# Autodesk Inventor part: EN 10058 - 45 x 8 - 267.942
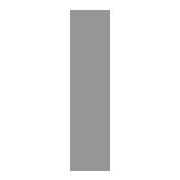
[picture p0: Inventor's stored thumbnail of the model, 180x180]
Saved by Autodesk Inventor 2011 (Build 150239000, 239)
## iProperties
Created: 2010-02
Part Number: EN 10058 - 45 x 8 - 267.942
Material: Steel, Mild
Description: flat steel bar 45*8
Document SubType Name: Modeling
Standard: DIN
Designer: PC
Standard Revision: 2004
Standards Organization: DIN
Language: en-US
Size Designation: 45 x 8
Categories: <MemberInstance><Categories><Category DisplayName="Structural Shapes" InternalName="089c4875-fa83-4c05-b084-43b9cc11f5ed" Mnemonic="GRDR"><CategoryParameter Dis
Stock Number: 45 x 8
Density: 7.86 g/cm^3
IsCustomPart: 1
_CCFamilyMember: 49
_CCFamilyDisplayName: DIN EN 10058 - Hot rolled flat steel bars for general purposes
_FrameMemberDoc: Frame Member File
_Version: 15.0.0
_GetPNFromCC: 1
G_L: 267.942 mm
G_W: 8.000 mm
G_H: 45.000 mm
+CA0FB9A9-289B-43A0-BCB1-81F3ED1C0187+CUTDETAIL1: Cut
Author: PC
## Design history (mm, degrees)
node "Start plane"
node "End plane"
sketch "Sketch"
  geometry: L1 (4, -22.5)-(-4, -22.5); L2 (-4, -22.5)-(-4, 22.5); L3 (-4, 22.5)-(4, 22.5); L4 (4, 22.5)-(4, -22.5); L5 (-6, 0)-(8, 0); L6 (0, -30)-(0, 40); L7 (0, 54)-(0, -44) reference; L8 (-9.2, 0)-(13.2, 0) reference
  constraints: 12 end point, 2 collinear, 2 parallel, 1 horizontal, 1 perpendicular
  dimensions: "d0" = 45 distance between parallel lines of L3 L1 (= G_W); "d1" = 8 distance between parallel lines of L4 L2 (= G_H); "d4" = 4 distance between parallel lines of L6 L4 (= 0.5 x d1); "d5" = 22.5 distance between parallel lines of L5 L3 (= 0.5 x d0)
extrude "Body" new body sketch "Sketch" stored distance "d2" = 267.94229 (= G_L); taper "d3" = 0 deg
node "Driven Length"
  sketch "Sketch3"
    geometry: L1 (0, 0)-(10, 0) reference
    constraints: 2 end point, 1 horizontal
  workplane "Work Plane3"
  sketch "Sketch4"
    geometry: L1 (-2, -167.942)-(12, -167.942) reference; L2 (-2, 100)-(12, 100) reference
    dimensions: "d9" = 267.94229 distance between parallel lines of L1 L2 (derived)
workplane "Work Plane4"
split "Split1"
body "Solid1"
other parameters: "G_W" = 45 [user parameter; used in 1 equation term], "G_H" = 8 [user parameter; used in 1 equation term], "G_L" = 267.94229 (= d9) [user parameter; used in 1 equation term], "G_OFFSET_START" = 167.94229 [user parameter; used in 1 equation term], "G_OFFSET_END" = 0 [user parameter; used in 1 equation term], "d6" = -167.94229 (= -G_OFFSET_START), "d8" = 90 deg, "MAS" = 0.283 [user parameter]
